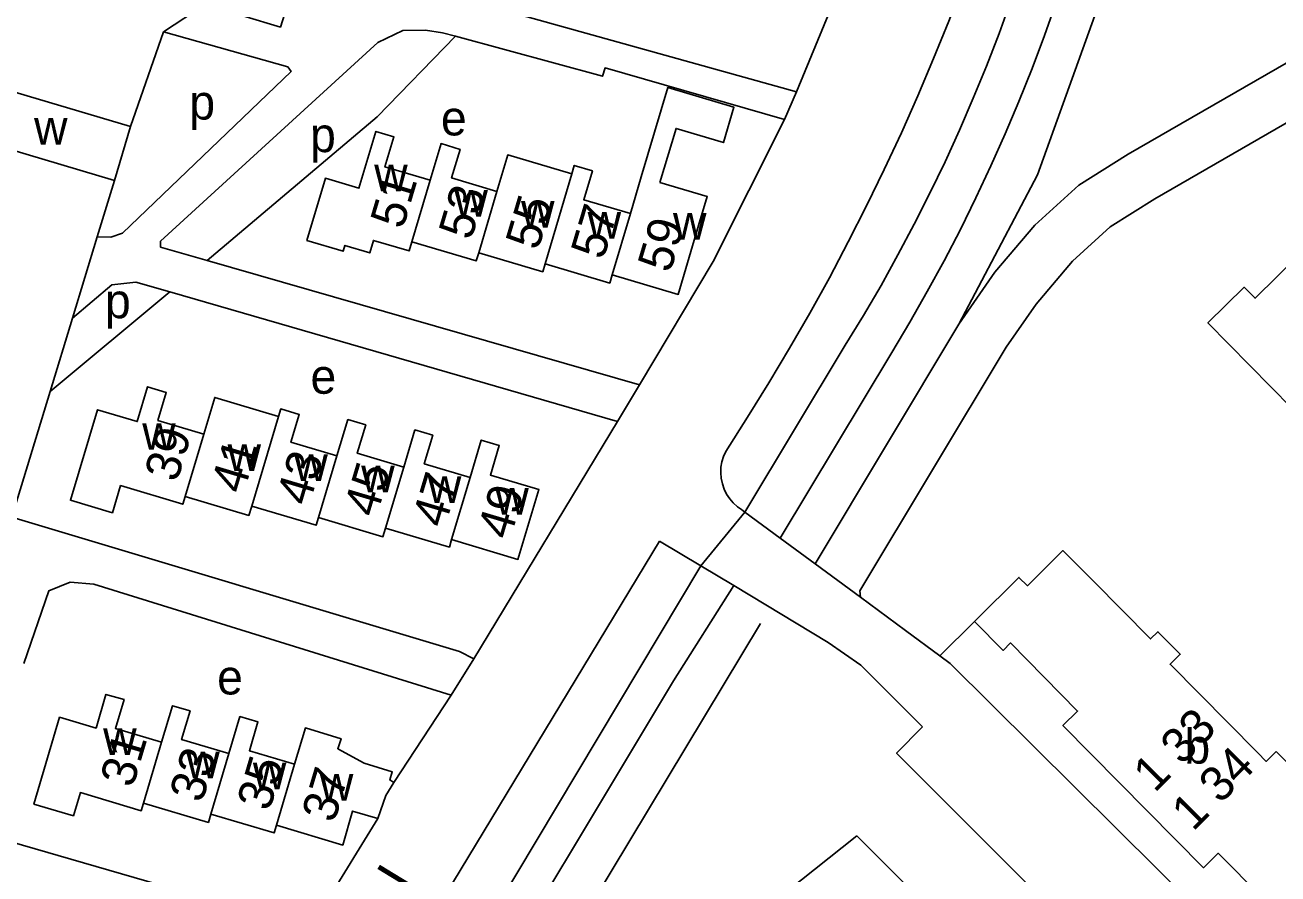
# Model space of a CAD drawing. Extents: x 161773 to 163836, y 384796 to 386521.
# Drawn here: x 162783.7 to 162928.2, y 386020.7 to 386118.6 of the extents above; entities that cross this region are included whole.
import ezdxf

# ---------------------------------------------------------------- set-up
doc = ezdxf.new("R2010")
doc.units = 0
for name, color, linetype in [('BLT_Basislijn', 7, 'Continuous'), ('BLT_Bebouwing', 7, 'Continuous'), ('BLT_Centroide', 7, 'Continuous'), ('BLT_Huisnummer', 7, 'Continuous'), ('BLT_Huisnummer_ tussenligend', 7, 'Continuous'), ('BLT_Huisnummer_reeks', 7, 'Continuous'), ('BLT_Onderverdeling_panden', 7, 'Continuous'), ('BLT_Straatnaam', 7, 'Continuous'), ('BLT_Vlakafsluiter', 7, 'Continuous')]:
    doc.layers.add(name, color=color, linetype=linetype)

msp = doc.modelspace()

# ---------------------------------------------------------------- linework, layer by layer
at = {"layer": 'BLT_Basislijn'}
for p, q in [((162799.65, 386117.82), (162804.46, 386120.98)), ((162872.7, 386110.89), (162836.94, 386120.84)), ((162872.7, 386110.89), (162876.61, 386120.4)), ((162795.86, 386106.88), (162799.65, 386117.82)), ((162871.29, 386107.71), (162872.7, 386110.89)), ((162794, 386100.64), (162792.02, 386094.15)), ((162792.02, 386094.15), (162789.17, 386084.77)), ((162854.57, 386077.1), (162804.7, 386091.44)), ((162786.6, 386076.33), (162800.4, 386087.81)), ((162800.4, 386087.81), (162852.02, 386072.84)), ((162789.17, 386084.77), (162786.6, 386076.33)), ((162891.41, 386084.07), (162874.85, 386056.43)), ((162878.32, 386081.67), (162866.74, 386062.41)), ((162883.68, 386080.82), (162870.8, 386059.41)), ((162854.57, 386077.1), (162852.02, 386072.84)), ((162786.6, 386076.33), (162782.17, 386061.82)), ((162852.02, 386072.84), (162835.47, 386045.46)), ((162866.33, 386062.71), (162866.74, 386062.41)), ((162866.74, 386062.41), (162870.8, 386059.41)), ((162856.89, 386059.07), (162861.67, 386056.19)), ((162870.8, 386059.41), (162874.85, 386056.43)), ((162861.67, 386056.19), (162865.45, 386053.92)), ((162880.07, 386052.58), (162885.25, 386048.76)), ((162812.36, 385956.3), (162868.52, 386049.55)), ((162893.24, 386049.79), (162889.23, 386045.83)), ((162885.25, 386048.76), (162889.23, 386045.83)), ((162832.86, 386041.3), (162835.47, 386045.46)), ((162889.23, 386045.83), (162890.42, 386044.95)), ((162826.23, 386031.22), (162832.86, 386041.3)), ((162816.59, 386014.4), (162824.4, 386027.07)), ((162777.98, 386025.55), (162816.59, 386014.4))]:
    msp.add_line(p, q, dxfattribs=at)
for points in [[(162891.41, 386084.07), (162900.49, 386101.33), (162907.09, 386119.69), (162909.24, 386126.41), (162910.61, 386127.86), (162911.99, 386128.24), (162913.24, 386128.93), (162914.19, 386130.86), (162915.62, 386140.02), (162921.03, 386199.73), (162921.72, 386202.82), (162923.32, 386205.55), (162925.68, 386207.66), (162928.62, 386208.84), (162931.78, 386208.87), (162934.86, 386208.12), (162937.62, 386206.58), (162939.89, 386204.37), (162994.17, 386149.84)], [(162828.2, 386166.09), (162813.15, 386118.36), (162804.46, 386120.98)], [(162864.52, 386069.41), (162867.05, 386073.34), (162869.51, 386077.3), (162871.9, 386081.31), (162874.23, 386085.36), (162876.48, 386089.44), (162878.66, 386093.57), (162880.77, 386097.73), (162882.82, 386101.93), (162884.79, 386106.16), (162886.68, 386110.43), (162888.5, 386114.72), (162890.25, 386119.05), (162891.93, 386123.41), (162893.53, 386127.79), (162894.4, 386130.3)], [(162878.32, 386081.67), (162880.42, 386085.09), (162882.44, 386088.56), (162884.39, 386092.07), (162886.27, 386095.61), (162888.08, 386099.2), (162889.82, 386102.81), (162891.49, 386106.46), (162893.08, 386110.15), (162894.61, 386113.86), (162896.05, 386117.61), (162897.42, 386121.38), (162898.72, 386125.18), (162899.44, 386127.43)], [(162883.68, 386080.82), (162885.76, 386084.31), (162887.77, 386087.84), (162889.71, 386091.41), (162891.59, 386095.02), (162893.39, 386098.66), (162895.12, 386102.34), (162896.77, 386106.05), (162898.35, 386109.79), (162899.86, 386113.57), (162901.29, 386117.37), (162902.65, 386121.2), (162903.93, 386125.06), (162904.21, 386125.92)], [(162891.41, 386084.07), (162895.57, 386090.07), (162900.2, 386095.51), (162905.25, 386100.13), (162910.94, 386103.68), (162945.41, 386123.56), (162949.04, 386124.58), (162951.83, 386124.4), (162954.63, 386122.85), (163042.34, 386034.58), (163043.57, 386033.88), (163045.39, 386033.72), (163046.93, 386034.22)], [(162792.02, 386094.15), (162793.59, 386094.12), (162794.95, 386094.58), (162814.38, 386113.23), (162813.99, 386113.77), (162799.65, 386117.82)], [(162804.7, 386091.44), (162799.32, 386092.98), (162799.32, 386093.65), (162824.39, 386116.57), (162827.27, 386117.96), (162829.89, 386118.01), (162831.85, 386117.7), (162833.34, 386117.3)], [(162896.88, 386081.43), (162900.33, 386086.41), (162904.53, 386091.34), (162908.89, 386095.33), (162914.03, 386098.53), (162947.76, 386117.99), (162949.68, 386118.53), (162950.09, 386118.5), (162950.97, 386118.02), (163038.09, 386030.35), (163038.73, 386029.11), (163039.01, 386027.51), (163038.68, 386026.09)], [(162804.7, 386091.44), (162824.33, 386107.99), (162833.34, 386117.3)], [(162833.34, 386117.3), (162850.31, 386112.68), (162850.6, 386113.64), (162871.29, 386107.71)], [(162854.57, 386077.1), (162863.08, 386091.33), (162871.29, 386107.71)], [(162789.17, 386084.77), (162793.69, 386088.62), (162796.49, 386088.94), (162800.4, 386087.81)], [(162896.88, 386081.43), (162879.99, 386053.34), (162880.07, 386052.58)], [(162864.52, 386069.41), (162864.26, 386068.83), (162864.08, 386068.21), (162863.97, 386067.58), (162863.95, 386066.94), (162864, 386066.3), (162864.14, 386065.67), (162864.35, 386065.06), (162864.63, 386064.49), (162864.99, 386063.95), (162865.4, 386063.47), (162865.88, 386063.03), (162866.33, 386062.71)], [(162782.17, 386061.82), (162833.81, 386046.33), (162835.47, 386045.46)], [(162644.59, 385677.96), (162641.67, 385679.15), (162641.76, 385680.04), (162652.61, 385700), (162710.55, 385805.08), (162711.1, 385806.51), (162756.83, 385887.63), (162796.99, 385960.06), (162856.89, 386059.07)], [(162861.67, 386056.19), (162795.28, 385945.23), (162766.85, 385893.4), (162734.28, 385835.66), (162683.66, 385744.84), (162659.11, 385700), (162646.79, 385677.52), (162644.59, 385677.96)], [(162783.57, 386044.95), (162786.42, 386053.34), (162788.91, 386054.31), (162791.62, 386054.09), (162832.86, 386041.3)], [(162865.45, 386053.92), (162858.49, 386042.92), (162807.81, 385958.51), (162798.15, 385940.14)], [(162865.45, 386053.92), (162876.34, 386047.38), (162880.11, 386044.76), (162887.24, 386037.62)], [(162973.8, 385984.96), (162971.9, 385987.09), (162965.35, 385994.11), (162961.15, 385996.93), (162958.25, 385998.29), (162951.03, 385999.71), (162938.83, 386000.22), (162933.58, 386002.14), (162890.42, 386044.95)], [(162887.24, 386037.62), (162884.23, 386034.61), (162925.23, 385993.59)]]:
    msp.add_lwpolyline(points, dxfattribs=at)
msp.add_lwpolyline([(162879.63, 386025.07), (162871.57, 386018.63), (162855.62, 385982.78), (162891.77, 385960.95), (162896.83, 385956.99), (162897.24, 385952.74), (162895.78, 385949.48), (162900.79, 385943.25), (162921.28, 385960.95), (162926.4, 385969.1), (162929.2, 385977.6), (162928.96, 385981.55), (162926.05, 385984.41), (162918.16, 385986.52)], close=True, dxfattribs=at)
at = {"layer": 'BLT_Bebouwing'}
for p, q in [((162775.44, 386112.96), (162795.86, 386106.88)), ((162795.86, 386106.88), (162794, 386100.64)), ((162893.24, 386049.79), (162893.4, 386049.96))]:
    msp.add_line(p, q, dxfattribs=at)
for points in [[(162794, 386100.64), (162773.58, 386106.72), (162775.44, 386112.96)], [(162854.78, 386101.08), (162857.84, 386111.38), (162865.46, 386109.11), (162864.25, 386105.04), (162858.79, 386106.66), (162856.93, 386100.43)], [(162828.32, 386093.59), (162828.01, 386092.54), (162823.88, 386093.74), (162823.45, 386092.3), (162820.59, 386093.16), (162820.4, 386092.5), (162816.21, 386093.74), (162818.34, 386100.91), (162822.21, 386099.76), (162824.16, 386106.32), (162826.24, 386105.7), (162825.21, 386102.23), (162830.43, 386100.68)], [(162830.43, 386100.68), (162831.68, 386104.91), (162833.87, 386104.25), (162832.89, 386100.96), (162838.13, 386099.4)], [(162838.13, 386099.4), (162839.38, 386103.61), (162846.76, 386101.41)], [(162846.76, 386101.41), (162847.05, 386102.39), (162849.14, 386101.77), (162848.15, 386098.43), (162853.52, 386096.84)], [(162856.93, 386100.43), (162862.4, 386098.81), (162861.4, 386095.48), (162859.04, 386087.51), (162851.42, 386089.77)], [(162853.52, 386096.84), (162854.78, 386101.08)], [(162836.03, 386092.33), (162835.75, 386091.38), (162828.32, 386093.59)], [(162843.68, 386091.04), (162843.41, 386090.13), (162836.03, 386092.33)], [(162929.83, 386074.38), (162920.15, 386084.24), (162924.34, 386088.35), (162925.59, 386087.08), (162930.69, 386092.09)], [(162851.42, 386089.77), (162851.14, 386088.83), (162843.68, 386091.04)], [(162802.16, 386064.22), (162801.89, 386063.31), (162794.71, 386065.46), (162793.78, 386062.33), (162788.92, 386063.78), (162792.04, 386074.22), (162796.63, 386072.85), (162797.82, 386076.86), (162799.98, 386076.21), (162799.02, 386072.99), (162804.31, 386071.41)], [(162804.31, 386071.41), (162805.57, 386075.64), (162812.93, 386073.44)], [(162812.93, 386073.44), (162813.19, 386074.31), (162815.32, 386073.68), (162814.36, 386070.47), (162819.67, 386068.88)], [(162819.67, 386068.88), (162820.93, 386073.08), (162823, 386072.46), (162822.02, 386069.2), (162827.38, 386067.6)], [(162827.38, 386067.6), (162828.66, 386071.89), (162830.73, 386071.27), (162829.75, 386067.98), (162835.04, 386066.4)], [(162835.04, 386066.4), (162836.33, 386070.72), (162838.4, 386070.1), (162837.38, 386066.68), (162842.97, 386065.01), (162840.56, 386056.95), (162832.9, 386059.24)], [(162809.84, 386063.1), (162809.52, 386062.02), (162802.16, 386064.22)], [(162817.55, 386061.79), (162817.28, 386060.88), (162809.84, 386063.1)], [(162825.28, 386060.56), (162824.98, 386059.57), (162817.55, 386061.79)], [(162832.9, 386059.24), (162832.64, 386058.36), (162825.28, 386060.56)], [(162893.4, 386049.96), (162898.35, 386054.86), (162899.33, 386053.91), (162903.43, 386057.97), (162906.95, 386054.42), (162913.53, 386047.77), (162914.39, 386048.61), (162916.96, 386046.01), (162915.78, 386044.86), (162925.88, 386034.66)], [(162928.02, 386034.78), (162930.59, 386032.17), (162929.75, 386031.34), (162937.49, 386023.54), (162938.35, 386024.34), (162941.64, 386021.02), (162940.09, 386019.49), (162936.53, 386015.97), (162935.58, 386016.95), (162931.46, 386012.86), (162921.35, 386023.04), (162919.63, 386021.37), (162903.43, 386037.77), (162905.11, 386039.44), (162897.39, 386047.31), (162896.54, 386046.45), (162893.24, 386049.79)], [(162799.45, 386035.86), (162794.12, 386037.44), (162795.11, 386040.77), (162793.03, 386041.38), (162791.88, 386037.49), (162787.68, 386038.74), (162784.71, 386028.73), (162789.27, 386027.38), (162790.07, 386030.04), (162797.1, 386027.95), (162797.36, 386028.83)], [(162799.45, 386035.86), (162800.7, 386040.07), (162802.73, 386039.46), (162801.75, 386036.17), (162807.21, 386034.55)], [(162807.21, 386034.55), (162808.48, 386038.82), (162810.56, 386038.21), (162809.57, 386034.88), (162814.79, 386033.33)], [(162814.79, 386033.33), (162816.03, 386037.5), (162820.15, 386036.25), (162819.77, 386035.11), (162822.8, 386033.45), (162826.05, 386032.46), (162825.76, 386031.5), (162826.23, 386031.22)], [(162925.88, 386034.66), (162926.88, 386033.64), (162928.02, 386034.78)], [(162826.23, 386031.22), (162825.32, 386029.7), (162824.4, 386027.07)], [(162805.14, 386027.56), (162804.85, 386026.6), (162797.36, 386028.83)], [(162824.4, 386027.07), (162821.48, 386027.92), (162820.34, 386024), (162812.69, 386026.28)], [(162812.69, 386026.28), (162812.44, 386025.4), (162805.14, 386027.56)]]:
    msp.add_lwpolyline(points, dxfattribs=at)
at = {"layer": 'BLT_Onderverdeling_panden'}
for p, q in [((162830.43, 386100.68), (162828.32, 386093.59)), ((162846.76, 386101.41), (162843.68, 386091.04)), ((162838.13, 386099.4), (162836.03, 386092.33)), ((162853.52, 386096.84), (162851.42, 386089.77)), ((162812.93, 386073.44), (162809.84, 386063.1)), ((162804.31, 386071.41), (162802.16, 386064.22)), ((162819.67, 386068.88), (162817.55, 386061.79)), ((162827.38, 386067.6), (162825.28, 386060.56)), ((162835.04, 386066.4), (162832.9, 386059.24)), ((162799.45, 386035.86), (162797.36, 386028.83)), ((162807.21, 386034.55), (162805.14, 386027.56)), ((162812.69, 386026.28), (162814.79, 386033.33))]:
    msp.add_line(p, q, dxfattribs=at)
at = {"layer": 'BLT_Vlakafsluiter'}
for p, q in [((162861.67, 386056.19), (162866.74, 386062.41)), ((162874.85, 386056.43), (162880.07, 386052.58))]:
    msp.add_line(p, q, dxfattribs=at)

# ---------------------------------------------------------------- texts
at = {"layer": 'BLT_Centroide'}
for s, p in [('p', (162802.64, 386107.69)), ('e', (162831.67, 386105.86)), ('w', (162784.73, 386104.81)), ('p', (162816.57, 386103.93)), ('w', (162823.97, 386099.41)), ('w', (162833.22, 386096.5)), ('w', (162840.91, 386095.23)), ('w', (162848.59, 386093.95)), ('w', (162858.44, 386093.84)), ('p', (162792.91, 386084.77)), ('e', (162816.62, 386076.06)), ('w', (162797.21, 386069.59)), ('w', (162807.05, 386067.16)), ('w', (162814.75, 386065.98)), ('w', (162822.47, 386064.69)), ('w', (162830.16, 386063.47)), ('w', (162837.94, 386062.12)), ('e', (162805.85, 386041.37)), ('w', (162792.7, 386034.38)), ('b', (162917.44, 386033.39)), ('w', (162802.28, 386031.69)), ('w', (162809.97, 386030.44)), ('w', (162817.7, 386029.12))]:
    msp.add_text(s, height=4, dxfattribs=at).set_placement(p)
at = {"layer": 'BLT_Huisnummer'}
for s, rotation, p in [('51', 73.4456, (162827.27, 386094.93)), ('55', 73.4474, (162842.87, 386092.49)), ('59', 73.4538, (162858.11, 386089.89)), ('39', 73.3728, (162801.22, 386065.74)), ('43', 73.3754, (162816.44, 386062.99)), ('49', 73.3654, (162839.63, 386059.09)), ('31', 73.4752, (162796.11, 386030.49)), ('37', 73.4688, (162819.36, 386026.44))]:
    msp.add_text(s, height=4, rotation=rotation, dxfattribs=at).set_placement(p)
at = {"layer": 'BLT_Huisnummer_ tussenligend'}
for s, rotation, p in [('53', 73.4456, (162835.15, 386093.66)), ('57', 73.4474, (162850.4, 386091.4)), ('41', 73.3728, (162808.88, 386064.38)), ('45', 73.3754, (162824.21, 386061.67)), ('47', 73.3754, (162832.1, 386060.46)), ('33', 73.4752, (162804.11, 386028.75)), ('35', 73.4752, (162811.88, 386027.79))]:
    msp.add_text(s, height=4, rotation=rotation, dxfattribs=at).set_placement(p)
at = {"layer": 'BLT_Huisnummer_reeks'}
for s, p in [('1 33', (162914.01, 386029.93)), ('1 34', (162918.44, 386025.49))]:
    msp.add_text(s, height=4, rotation=45.244, dxfattribs=at).set_placement(p)
at = {"layer": 'BLT_Straatnaam'}
msp.add_text('AMAZONENLAAN', height=5, rotation=58.6452, dxfattribs=at).set_placement((162800.38, 385972.31))

doc.saveas('drawing.dxf')
